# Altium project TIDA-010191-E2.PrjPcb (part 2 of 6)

## Sheet TIDA-010191-E2_LMK04832.SchDoc: LMK0482x
size 558 x 431 mm; Date: Not shown in title block; ApprovedBy: Not shown in title block; CheckedBy: Not shown in title block; Author: Not shown in title block; CompanyName: Not shown in title block; DrawnBy: Avinash N; Engineer: Not shown in title block; Organization: Not shown in title block; Address1: Not shown in title block; Address2: Not shown in title block; Address3: Not shown in title block; Address4: Not shown in title block; DocumentNumber: 2; Revision: Use project parameter SCH_Rev; SheetNumber: 2; SheetTotal: 9; PageSetup: Record=PageOptions¦CenterHorizontal=True¦CenterVertical=True¦PrintScale=1.00¦XCorrection=1.00¦YCorrection=1.00¦PrintKind=0¦BorderSize=5000000¦LeftOffset=0¦BottomOffset=0¦Orientation=2¦PaperLength=1000¦PaperWidth=1000¦Scale=100¦PaperSource=15¦PrintQuality=600¦MediaType=1¦DitherType=10¦PaperKind=Letter¦PrintScaleMode=1
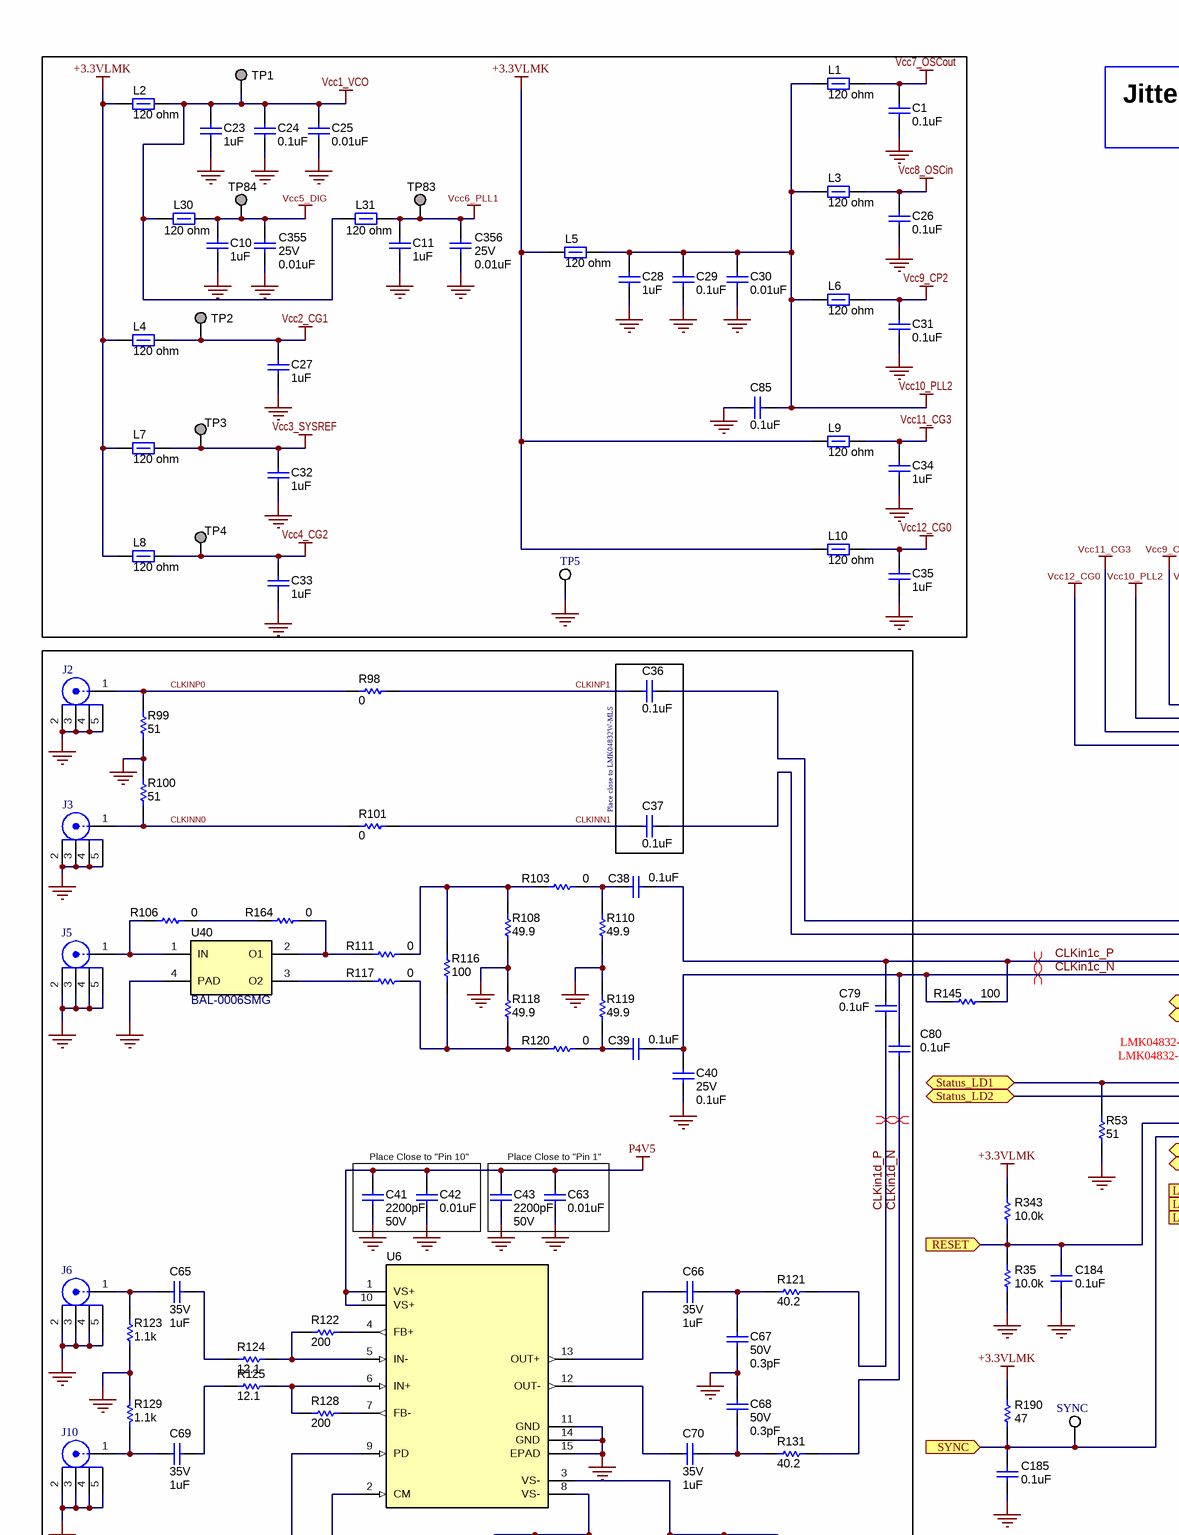
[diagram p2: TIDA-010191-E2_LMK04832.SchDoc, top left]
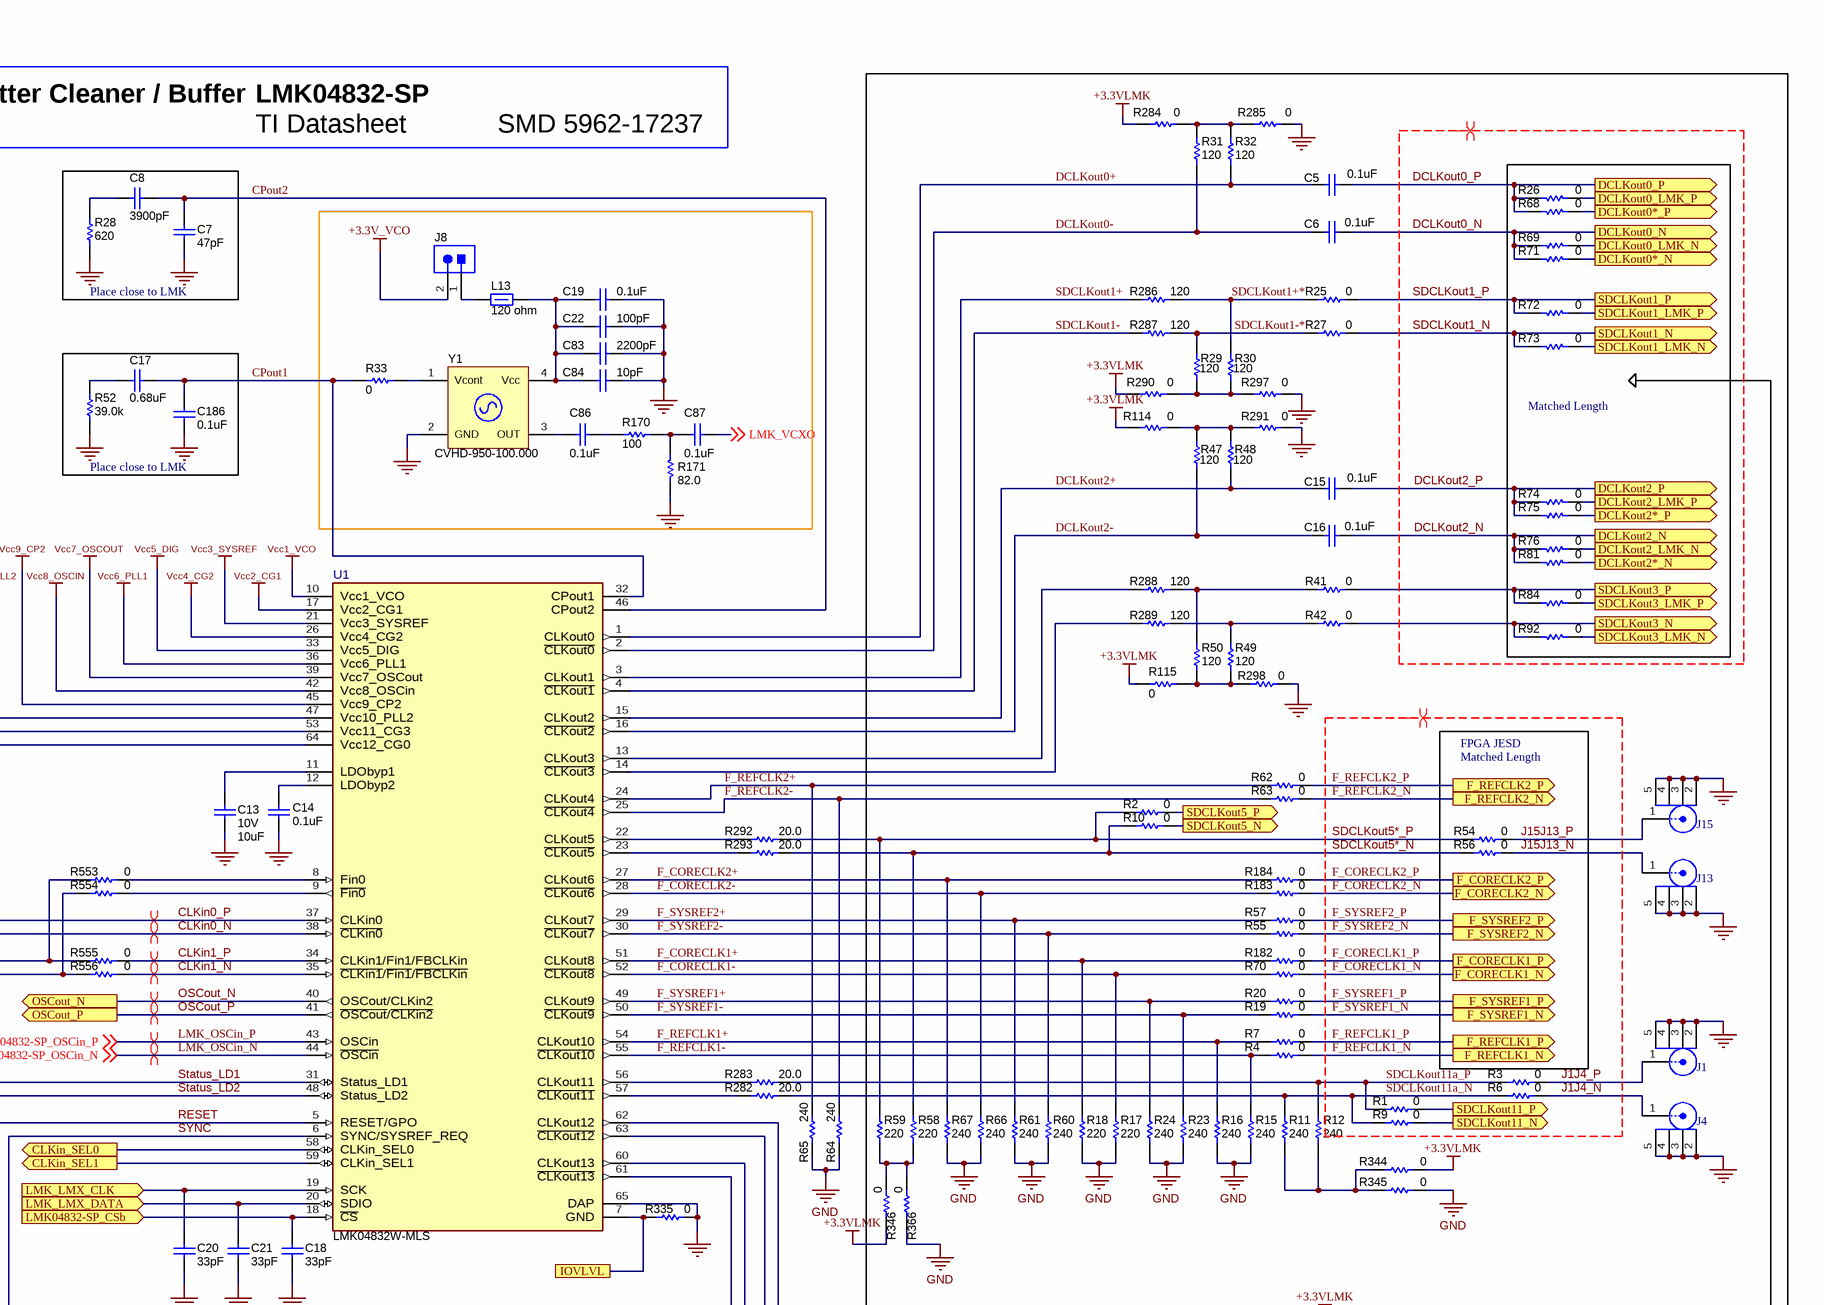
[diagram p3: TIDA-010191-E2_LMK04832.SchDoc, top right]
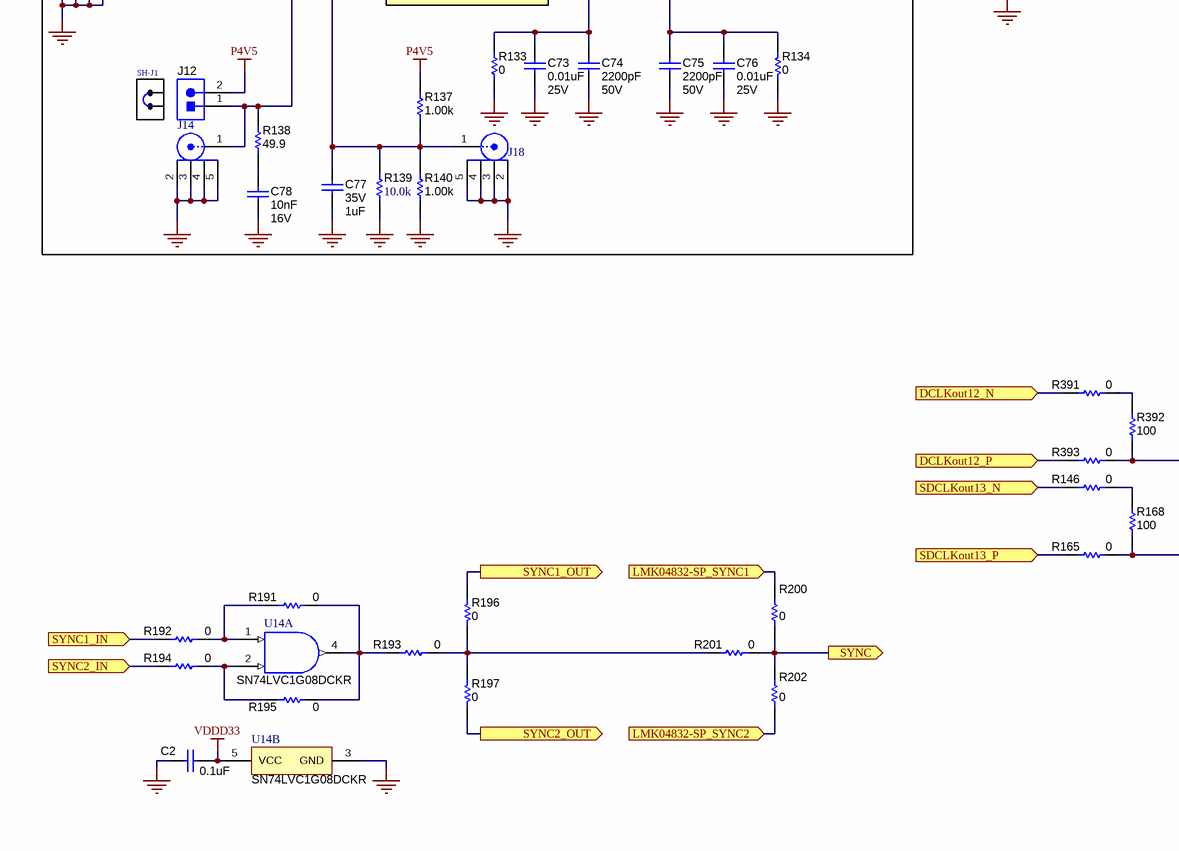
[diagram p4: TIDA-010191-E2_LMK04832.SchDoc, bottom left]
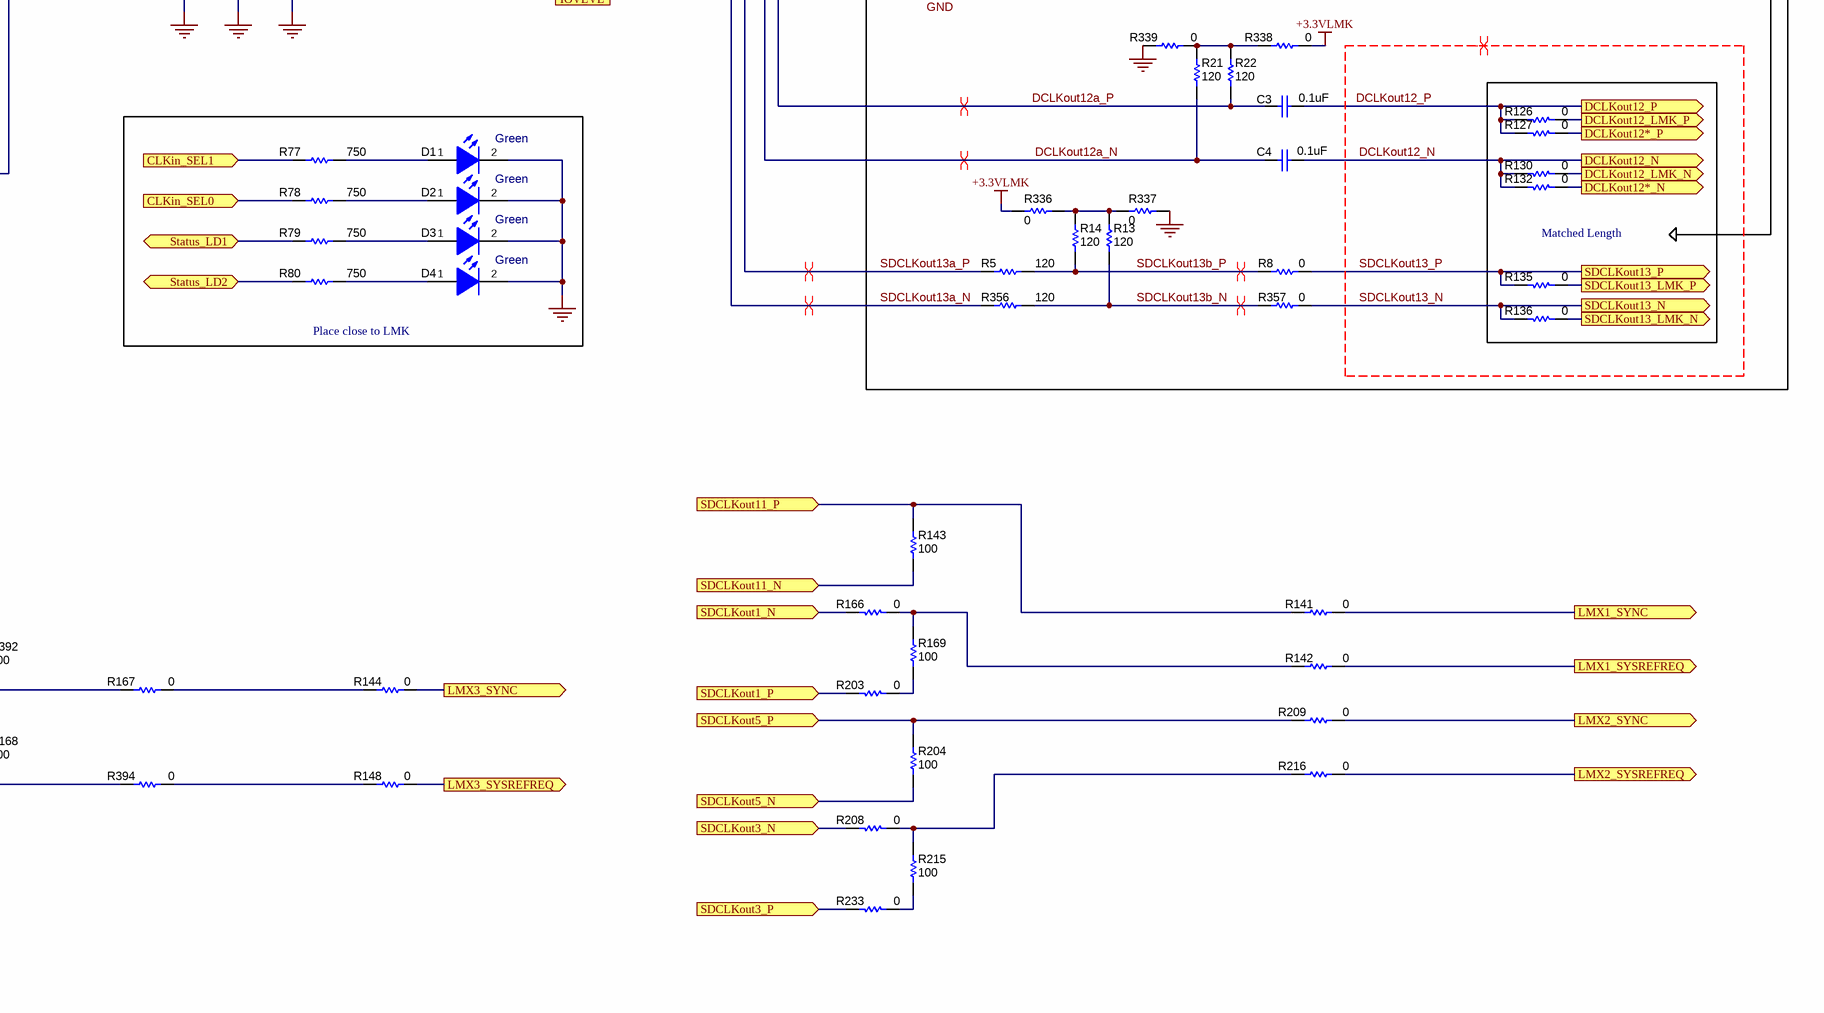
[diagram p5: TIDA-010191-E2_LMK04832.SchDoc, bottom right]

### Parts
C1  ValueDisplayed: 0.1uF  [0402]  (hidden comment: Capacitor)
C2  ValueDisplayed: 0.1uF  [0402]  (hidden comment: Capacitor)
C3  ValueDisplayed: 0.1uF  [0402]  (hidden comment: Capacitor)
C4  ValueDisplayed: 0.1uF  [0402]  (hidden comment: Capacitor)
C5  ValueDisplayed: 0.1uF  [0402]  (hidden comment: Capacitor)
C6  ValueDisplayed: 0.1uF  [0402]  (hidden comment: Capacitor)
C7  ValueDisplayed: 47pF  [0201_033]  (hidden comment: Capacitor)
C8  ValueDisplayed: 3900pF  [0201]  (hidden comment: Capacitor)
C10  ValueDisplayed: 1uF  [0402]  (hidden comment: Capacitor)
C11  ValueDisplayed: 1uF  [0402]  (hidden comment: Capacitor)
C13  VDC_V: 10V  ValueDisplayed: 10uF  [0805_HV]  (hidden comment: CMP-0007732-2)
C14  ValueDisplayed: 0.1uF  [0603]  (hidden comment: Capacitor)
C15  ValueDisplayed: 0.1uF  [0402]  (hidden comment: Capacitor)
C16  ValueDisplayed: 0.1uF  [0402]  (hidden comment: Capacitor)
C17  ValueDisplayed: 0.68uF  [0402]  (hidden comment: Capacitor)
C18  ValueDisplayed: 33pF  [0603L]  (hidden comment: Capacitor)
C19  ValueDisplayed: 0.1uF  [0402]  (hidden comment: Capacitor)
C20  ValueDisplayed: 33pF  [0603L]  (hidden comment: Capacitor)
C21  ValueDisplayed: 33pF  [0603L]  (hidden comment: Capacitor)
C22  ValueDisplayed: 100pF  [0402]  (hidden comment: CMP-0006196-2)
C23  ValueDisplayed: 1uF  [0402]  (hidden comment: Capacitor)
C24  ValueDisplayed: 0.1uF  [0402]  (hidden comment: Capacitor)
C25  ValueDisplayed: 0.01uF  [0402]  (hidden comment: Capacitor)
C26  ValueDisplayed: 0.1uF  [0402]  (hidden comment: Capacitor)
C27  ValueDisplayed: 1uF  [0402]  (hidden comment: Capacitor)
C28  ValueDisplayed: 1uF  [0402]  (hidden comment: Capacitor)
C29  ValueDisplayed: 0.1uF  [0402]  (hidden comment: Capacitor)
C30  ValueDisplayed: 0.01uF  [0402]  (hidden comment: Capacitor)
C31  ValueDisplayed: 0.1uF  [0402]  (hidden comment: Capacitor)
C32  ValueDisplayed: 1uF  [0402]  (hidden comment: Capacitor)
C33  ValueDisplayed: 1uF  [0402]  (hidden comment: Capacitor)
C34  ValueDisplayed: 1uF  [0402]  (hidden comment: Capacitor)
C35  ValueDisplayed: 1uF  [0402]  (hidden comment: Capacitor)
C36  ValueDisplayed: 0.1uF  [0201_033]  (hidden comment: Capacitor)
C37  ValueDisplayed: 0.1uF  [0201_033]  (hidden comment: Capacitor)
C38  ValueDisplayed: 0.1uF  [0402]  (hidden comment: Capacitor)
C39  ValueDisplayed: 0.1uF  [0402]  (hidden comment: Capacitor)
C40  VDC_V: 25V  ValueDisplayed: 0.1uF  [0402]  (hidden comment: CMP-0006295-2)
C41  ValueDisplayed: 2200pF  VDC_V: 50V  [0306]  (hidden comment: CMP-0009493-2)
C42  ValueDisplayed: 0.01uF  [0306]  (hidden comment: Capacitor)
C43  ValueDisplayed: 2200pF  VDC_V: 50V  [0306]  (hidden comment: CMP-0009493-2)
C63  ValueDisplayed: 0.01uF  [0306]  (hidden comment: Capacitor)
C65  VDC_V: 35V  ValueDisplayed: 1uF  [0402]  (hidden comment: GRM155R6YA105KE11D)
C66  VDC_V: 35V  ValueDisplayed: 1uF  [0402]  (hidden comment: GRM155R6YA105KE11D)
C67  VDC_V: 50V  ValueDisplayed: 0.3pF  [0402]  (hidden comment: 500R07S0R3BV4T)
C68  VDC_V: 50V  ValueDisplayed: 0.3pF  [0402]  (hidden comment: 500R07S0R3BV4T)
C69  VDC_V: 35V  ValueDisplayed: 1uF  [0402]  (hidden comment: GRM155R6YA105KE11D)
C70  VDC_V: 35V  ValueDisplayed: 1uF  [0402]  (hidden comment: GRM155R6YA105KE11D)
C73  ValueDisplayed: 0.01uF  VDC_V: 25V  [0306]  (hidden comment: CMP-0009490-2)
C74  ValueDisplayed: 2200pF  VDC_V: 50V  [0306]  (hidden comment: CMP-0009493-2)
C75  ValueDisplayed: 2200pF  VDC_V: 50V  [0306]  (hidden comment: CMP-0009493-2)
C76  ValueDisplayed: 0.01uF  VDC_V: 25V  [0306]  (hidden comment: CMP-0009490-2)
C77  VDC_V: 35V  ValueDisplayed: 1uF  [0402]  (hidden comment: GRM155R6YA105KE11D)
C78  Cap_F: 10nF  VDC_V: 16V  [0603]  (hidden comment: GRM188R71C103KA01D)
C79  ValueDisplayed: 0.1uF  [0402]  (hidden comment: Capacitor)
C80  ValueDisplayed: 0.1uF  [0402]  (hidden comment: Capacitor)
C83  ValueDisplayed: 2200pF  [0402]  (hidden comment: Capacitor)
C84  ValueDisplayed: 10pF  [0402]  (hidden comment: Capacitor)
C85  ValueDisplayed: 0.1uF  [0402]  (hidden comment: Capacitor)
C86  ValueDisplayed: 0.1uF  [0402]  (hidden comment: Capacitor)
C87  ValueDisplayed: 0.1uF  [0402]  (hidden comment: Capacitor)
C184  ValueDisplayed: 0.1uF  [0402]  (hidden comment: Capacitor)
C185  ValueDisplayed: 0.1uF  [0402]  (hidden comment: Capacitor)
C186  ValueDisplayed: 0.1uF  [0402]  (hidden comment: Capacitor)
C355  VDC_V: 25V  ValueDisplayed: 0.01uF  [0402]  (hidden comment: GRM155R71E103KA01D)
C356  VDC_V: 25V  ValueDisplayed: 0.01uF  [0402]  (hidden comment: GRM155R71E103KA01D)
D1  value Green  [LTST-C191_Green]  (hidden comment: LED)
D2  value Green  [LTST-C191_Green]  (hidden comment: LED)
D3  value Green  [LTST-C191_Green]  (hidden comment: LED)
D4  value Green  [LTST-C191_Green]  (hidden comment: LED)
J1  SMA_Contact1_GND2345  [Johnson_142-0701-20x]  (value not drawn)
J2  SMA_Contact1_GND2345  [Johnson_142-0701-20x]  (value not drawn)
J3  SMA_Contact1_GND2345  [Johnson_142-0701-20x]  (value not drawn)
J4  SMA_Contact1_GND2345  [Johnson_142-0701-20x]  (value not drawn)
J5  SMA_Contact1_GND2345  [Johnson_142-0701-20x]  (value not drawn)
J6  SMA_Contact1_GND2345  [Johnson_142-0701-20x]  (value not drawn)
J8  HTSW-102-07-G-S  [Samtec_HTSW-102-07-G-S]  (value not drawn)
J10  SMA_Contact1_GND2345  [Johnson_142-0701-20x]  (value not drawn)
J12  HTSW-102-07-G-S  [Samtec_HTSW-102-07-G-S]  (value not drawn)
J13  SMA_Contact1_GND2345  [Johnson_142-0701-20x]  (value not drawn)
J14  SMA_Contact1_GND2345  [Johnson_142-0701-20x]  (value not drawn)
J15  SMA_Contact1_GND2345  [Johnson_142-0701-20x]  (value not drawn)
J18  SMA_Contact1_GND2345  [Johnson_142-0701-20x]  (value not drawn)
L1  ValueDisplayed: 120 ohm  [0603]  (hidden comment: Ferrite_Bead)
L2  ValueDisplayed: 120 ohm  [0603]  (hidden comment: Ferrite_Bead)
L3  ValueDisplayed: 120 ohm  [0603]  (hidden comment: Ferrite_Bead)
L4  ValueDisplayed: 120 ohm  [0603]  (hidden comment: Ferrite_Bead)
L5  ValueDisplayed: 120 ohm  [0603]  (hidden comment: Ferrite_Bead)
L6  ValueDisplayed: 120 ohm  [0603]  (hidden comment: Ferrite_Bead)
L7  ValueDisplayed: 120 ohm  [0603]  (hidden comment: Ferrite_Bead)
L8  ValueDisplayed: 120 ohm  [0603]  (hidden comment: Ferrite_Bead)
L9  ValueDisplayed: 120 ohm  [0603]  (hidden comment: Ferrite_Bead)
L10  ValueDisplayed: 120 ohm  [0603]  (hidden comment: Ferrite_Bead)
L13  ValueDisplayed: 120 ohm  [0603]  (hidden comment: Ferrite_Bead)
L30  ValueDisplayed: 120 ohm  [0603]  (hidden comment: Ferrite_Bead)
L31  ValueDisplayed: 120 ohm  [0603]  (hidden comment: Ferrite_Bead)
R1  ValueDisplayed: 0  [0402]  (hidden comment: Resistor)
R2  ValueDisplayed: 0  [0402]  (hidden comment: Resistor)
R3  ValueDisplayed: 0  [0402]  (hidden comment: Resistor)
R4  ValueDisplayed: 0  [0402]  (hidden comment: Resistor)
R5  ValueDisplayed: 120  [0402]  (hidden comment: Resistor)
R6  ValueDisplayed: 0  [0402]  (hidden comment: Resistor)
R7  ValueDisplayed: 0  [0402]  (hidden comment: Resistor)
R8  ValueDisplayed: 0  [0402]  (hidden comment: Resistor)
R9  ValueDisplayed: 0  [0402]  (hidden comment: Resistor)
R10  ValueDisplayed: 0  [0402]  (hidden comment: Resistor)
R11  ValueDisplayed: 240  [0402]  (hidden comment: Resistor)
R12  ValueDisplayed: 240  [0402]  (hidden comment: Resistor)
R13  ValueDisplayed: 120  [0402]  (hidden comment: Resistor)
R14  ValueDisplayed: 120  [0402]  (hidden comment: Resistor)
R15  ValueDisplayed: 240  [0402]  (hidden comment: Resistor)
R16  ValueDisplayed: 240  [0402]  (hidden comment: Resistor)
R17  ValueDisplayed: 220  [0402]  (hidden comment: Resistor)
R18  ValueDisplayed: 220  [0402]  (hidden comment: Resistor)
R19  ValueDisplayed: 0  [0402]  (hidden comment: Resistor)
R20  ValueDisplayed: 0  [0402]  (hidden comment: Resistor)
R21  ValueDisplayed: 120  [0402]  (hidden comment: Resistor)
R22  ValueDisplayed: 120  [0402]  (hidden comment: Resistor)
R23  ValueDisplayed: 240  [0402]  (hidden comment: Resistor)
R24  ValueDisplayed: 240  [0402]  (hidden comment: Resistor)
R25  ValueDisplayed: 0  [0402]  (hidden comment: Resistor)
R26  ValueDisplayed: 0  [0402]  (hidden comment: CMP-0026822-3)
R27  ValueDisplayed: 0  [0402]  (hidden comment: Resistor)
R28  ValueDisplayed: 620  [0201]  (hidden comment: Resistor)
R29  ValueDisplayed: 120  [0402]  (hidden comment: Resistor)
R30  ValueDisplayed: 120  [0402]  (hidden comment: Resistor)
R31  ValueDisplayed: 120  [0402]  (hidden comment: Resistor)
R32  ValueDisplayed: 120  [0402]  (hidden comment: Resistor)
R33  ValueDisplayed: 0  [0402]  (hidden comment: Resistor)
R35  ValueDisplayed: 10.0k  [0402]  (hidden comment: Resistor)
R41  ValueDisplayed: 0  [0402]  (hidden comment: Resistor)
R42  ValueDisplayed: 0  [0402]  (hidden comment: Resistor)
R47  ValueDisplayed: 120  [0402]  (hidden comment: Resistor)
R48  ValueDisplayed: 120  [0402]  (hidden comment: Resistor)
R49  ValueDisplayed: 120  [0402]  (hidden comment: Resistor)
R50  ValueDisplayed: 120  [0402]  (hidden comment: Resistor)
R52  ValueDisplayed: 39.0k  [0201]  (hidden comment: Resistor)
R53  value 51  [0603L]  (hidden comment: Resistor)
R54  ValueDisplayed: 0  [0402]  (hidden comment: Resistor)
R55  ValueDisplayed: 0  [0402]  (hidden comment: Resistor)
R56  ValueDisplayed: 0  [0402]  (hidden comment: Resistor)
R57  ValueDisplayed: 0  [0402]  (hidden comment: Resistor)
R58  ValueDisplayed: 220  [0402]  (hidden comment: Resistor)
R59  ValueDisplayed: 220  [0402]  (hidden comment: Resistor)
R60  ValueDisplayed: 240  [0402]  (hidden comment: Resistor)
R61  ValueDisplayed: 240  [0402]  (hidden comment: Resistor)
R62  ValueDisplayed: 0  [0402]  (hidden comment: Resistor)
R63  ValueDisplayed: 0  [0402]  (hidden comment: Resistor)
R64  ValueDisplayed: 240  [0402]  (hidden comment: Resistor)
R65  ValueDisplayed: 240  [0402]  (hidden comment: Resistor)
R66  ValueDisplayed: 240  [0402]  (hidden comment: Resistor)
R67  ValueDisplayed: 240  [0402]  (hidden comment: Resistor)
R68  ValueDisplayed: 0  [0402]  (hidden comment: CMP-0026822-3)
R69  ValueDisplayed: 0  [0402]  (hidden comment: CMP-0026822-3)
R70  ValueDisplayed: 0  [0402]  (hidden comment: Resistor)
R71  ValueDisplayed: 0  [0402]  (hidden comment: CMP-0026822-3)
R72  ValueDisplayed: 0  [0402]  (hidden comment: CMP-0026822-3)
R73  ValueDisplayed: 0  [0402]  (hidden comment: CMP-0026822-3)
R74  ValueDisplayed: 0  [0402]  (hidden comment: CMP-0026822-3)
R75  ValueDisplayed: 0  [0402]  (hidden comment: CMP-0026822-3)
R76  ValueDisplayed: 0  [0402]  (hidden comment: CMP-0026822-3)
R77  ValueDisplayed: 750  [0603]  (hidden comment: Resistor)
R78  ValueDisplayed: 750  [0603]  (hidden comment: Resistor)
R79  ValueDisplayed: 750  [0603]  (hidden comment: Resistor)
R80  ValueDisplayed: 750  [0603]  (hidden comment: Resistor)
R81  ValueDisplayed: 0  [0402]  (hidden comment: CMP-0026822-3)
R84  ValueDisplayed: 0  [0402]  (hidden comment: CMP-0026822-3)
R92  ValueDisplayed: 0  [0402]  (hidden comment: CMP-0026822-3)
R98  ValueDisplayed: 0  [0201]  (hidden comment: CMP-0065361-1)
R99  ValueDisplayed: 51  [0201]  (hidden comment: RC0201JR-0751RL)
R100  ValueDisplayed: 51  [0201]  (hidden comment: RC0201JR-0751RL)
R101  ValueDisplayed: 0  [0201]  (hidden comment: CMP-0065361-1)
R103  ValueDisplayed: 0  [0201]  (hidden comment: ERJ-1GN0R00C)
R106  ValueDisplayed: 0  [0201]  (hidden comment: ERJ-1GN0R00C)
R108  ValueDisplayed: 49.9  [0603]  (hidden comment: CRCW060349R9FKEA)
R110  ValueDisplayed: 49.9  [0603]  (hidden comment: CRCW060349R9FKEA)
R111  ValueDisplayed: 0  [0201]  (hidden comment: ERJ-1GN0R00C)
R114  ValueDisplayed: 0  [0402]  (hidden comment: Resistor)
R115  ValueDisplayed: 0  [0402]  (hidden comment: Resistor)
R116  ValueDisplayed: 100  [0402]  (hidden comment: CRCW0402100RFKED)
R117  ValueDisplayed: 0  [0201]  (hidden comment: ERJ-1GN0R00C)
R118  ValueDisplayed: 49.9  [0603]  (hidden comment: CRCW060349R9FKEA)
R119  ValueDisplayed: 49.9  [0603]  (hidden comment: CRCW060349R9FKEA)
R120  ValueDisplayed: 0  [0201]  (hidden comment: ERJ-1GN0R00C)
R121  ValueDisplayed: 40.2  [0402]  (hidden comment: CRCW040240R2FKED)
R122  ValueDisplayed: 200  [0402]  (hidden comment: CRCW0402200RFKED)
R123  ValueDisplayed: 1.1k  [0402]  (hidden comment: CRCW04021K10JNED)
R124  ValueDisplayed: 12.1  [0402]  (hidden comment: CRCW040212R1FKED)
R125  ValueDisplayed: 12.1  [0402]  (hidden comment: CRCW040212R1FKED)
R126  ValueDisplayed: 0  [0402]  (hidden comment: CMP-0026822-3)
R127  ValueDisplayed: 0  [0402]  (hidden comment: CMP-0026822-3)
R128  ValueDisplayed: 200  [0402]  (hidden comment: CRCW0402200RFKED)
R129  ValueDisplayed: 1.1k  [0402]  (hidden comment: CRCW04021K10JNED)
R130  ValueDisplayed: 0  [0402]  (hidden comment: CMP-0026822-3)
R131  ValueDisplayed: 40.2  [0402]  (hidden comment: CRCW040240R2FKED)
R132  ValueDisplayed: 0  [0402]  (hidden comment: CMP-0026822-3)
R133  ValueDisplayed: 0  [0402]  (hidden comment: CRCW04020000Z0ED)
R134  ValueDisplayed: 0  [0402]  (hidden comment: CRCW04020000Z0ED)
R135  ValueDisplayed: 0  [0402]  (hidden comment: CMP-0026822-3)
R136  ValueDisplayed: 0  [0402]  (hidden comment: CMP-0026822-3)
R137  ValueDisplayed: 1.00k  [0603]  (hidden comment: CRCW06031K00FKEA)
R138  ValueDisplayed: 49.9  [0603]  (hidden comment: CRCW060349R9FKEA)
R139  ValueDisplayed: 10.0k  [0402]  (hidden comment: ERJ-2RKF1002X)
R140  ValueDisplayed: 1.00k  [0603]  (hidden comment: CRCW06031K00FKEA)
R141  ValueDisplayed: 0  [0402]  (hidden comment: Resistor)
R142  ValueDisplayed: 0  [0402]  (hidden comment: Resistor)
R143  ValueDisplayed: 100  [0402]  (hidden comment: CRCW0402100RFKED)
R144  ValueDisplayed: 0  [0402]  (hidden comment: Resistor)
R145  ValueDisplayed: 100  [0402]  (hidden comment: CRCW0402100RFKED)
R146  ValueDisplayed: 0  [0402]  (hidden comment: Resistor)
R148  ValueDisplayed: 0  [0402]  (hidden comment: Resistor)
R164  ValueDisplayed: 0  [0201]  (hidden comment: ERJ-1GN0R00C)
R165  ValueDisplayed: 0  [0402]  (hidden comment: Resistor)
R166  ValueDisplayed: 0  [0402]  (hidden comment: CMP-0026822-3)
R167  ValueDisplayed: 0  [0402]  (hidden comment: Resistor)
R168  ValueDisplayed: 100  [0402]  (hidden comment: CRCW0402100RFKED)
R169  ValueDisplayed: 100  [0402]  (hidden comment: CRCW0402100RFKED)
R170  ValueDisplayed: 100  [0402]  (hidden comment: CRCW0402100RFKED)
R171  ValueDisplayed: 82.0  [0603]  (hidden comment: Resistor)
R182  ValueDisplayed: 0  [0402]  (hidden comment: Resistor)
R183  ValueDisplayed: 0  [0402]  (hidden comment: Resistor)
R184  ValueDisplayed: 0  [0402]  (hidden comment: Resistor)
R190  ValueDisplayed: 47  [0402]  (hidden comment: Resistor)
R191  ValueDisplayed: 0  [0402]  (hidden comment: Resistor)
R192  ValueDisplayed: 0  [0402]  (hidden comment: Resistor)
R193  ValueDisplayed: 0  [0402]  (hidden comment: Resistor)
R194  ValueDisplayed: 0  [0402]  (hidden comment: Resistor)
R195  ValueDisplayed: 0  [0402]  (hidden comment: Resistor)
R196  ValueDisplayed: 0  [0402]  (hidden comment: Resistor)
R197  ValueDisplayed: 0  [0402]  (hidden comment: Resistor)
R200  ValueDisplayed: 0  [0402]  (hidden comment: Resistor)
R201  ValueDisplayed: 0  [0402]  (hidden comment: Resistor)
R202  ValueDisplayed: 0  [0402]  (hidden comment: Resistor)
R203  ValueDisplayed: 0  [0402]  (hidden comment: CMP-0026822-3)
R204  ValueDisplayed: 100  [0402]  (hidden comment: CRCW0402100RFKED)
R208  ValueDisplayed: 0  [0402]  (hidden comment: CMP-0026822-3)
R209  ValueDisplayed: 0  [0402]  (hidden comment: CMP-0026822-3)
R215  ValueDisplayed: 100  [0402]  (hidden comment: CRCW0402100RFKED)
R216  ValueDisplayed: 0  [0402]  (hidden comment: CMP-0026822-3)
R233  ValueDisplayed: 0  [0402]  (hidden comment: CMP-0026822-3)
R282  ValueDisplayed: 20.0  [0402]  (hidden comment: Resistor)
R283  ValueDisplayed: 20.0  [0402]  (hidden comment: Resistor)
R284  ValueDisplayed: 0  [0402]  (hidden comment: Resistor)
R285  ValueDisplayed: 0  [0402]  (hidden comment: Resistor)
R286  ValueDisplayed: 120  [0402]  (hidden comment: Resistor)
R287  ValueDisplayed: 120  [0402]  (hidden comment: Resistor)
R288  ValueDisplayed: 120  [0402]  (hidden comment: Resistor)
R289  ValueDisplayed: 120  [0402]  (hidden comment: Resistor)
R290  ValueDisplayed: 0  [0402]  (hidden comment: Resistor)
R291  ValueDisplayed: 0  [0402]  (hidden comment: Resistor)
R292  ValueDisplayed: 20.0  [0402]  (hidden comment: Resistor)
R293  ValueDisplayed: 20.0  [0402]  (hidden comment: Resistor)
R297  ValueDisplayed: 0  [0402]  (hidden comment: Resistor)
R298  ValueDisplayed: 0  [0402]  (hidden comment: Resistor)
R335  ValueDisplayed: 0  [0402]  (hidden comment: Resistor)
R336  ValueDisplayed: 0  [0402]  (hidden comment: Resistor)
R337  ValueDisplayed: 0  [0402]  (hidden comment: Resistor)
R338  ValueDisplayed: 0  [0402]  (hidden comment: Resistor)
R339  ValueDisplayed: 0  [0402]  (hidden comment: Resistor)
R343  ValueDisplayed: 10.0k  [0402]  (hidden comment: Resistor)
R344  ValueDisplayed: 0  [0402]  (hidden comment: Resistor)
R345  ValueDisplayed: 0  [0402]  (hidden comment: Resistor)
R346  ValueDisplayed: 0  [0402]  (hidden comment: Resistor)
R356  ValueDisplayed: 120  [0402]  (hidden comment: Resistor)
R357  ValueDisplayed: 0  [0402]  (hidden comment: Resistor)
R366  ValueDisplayed: 0  [0402]  (hidden comment: Resistor)
R391  ValueDisplayed: 0  [0402]  (hidden comment: Resistor)
R392  ValueDisplayed: 100  [0402]  (hidden comment: CRCW0402100RFKED)
R393  ValueDisplayed: 0  [0402]  (hidden comment: Resistor)
R394  ValueDisplayed: 0  [0402]  (hidden comment: Resistor)
R553  ValueDisplayed: 0  [0201]  (hidden comment: ERJ-1GN0R00C)
R554  ValueDisplayed: 0  [0201]  (hidden comment: ERJ-1GN0R00C)
R555  ValueDisplayed: 0  [0201]  (hidden comment: ERJ-1GN0R00C)
R556  ValueDisplayed: 0  [0201]  (hidden comment: ERJ-1GN0R00C)
SH-J1  SPC02SYAN  [SPC02SYAN]  (value not drawn)
SYNC  5007  [Keystone5007]  (value not drawn)
TP1  1573-2  [Keystone1573-2]  (value not drawn)
TP2  1573-2  [Keystone1573-2]  (value not drawn)
TP3  1573-2  [Keystone1573-2]  (value not drawn)
TP4  1573-2  [Keystone1573-2]  (value not drawn)
TP5  5015  [Testpoint_Keystone_Miniature]  (value not drawn)
TP83  1573-2  [Keystone1573-2]  (value not drawn)
TP84  1573-2  [Keystone1573-2]  (value not drawn)
U1  LMK04832W-MLS  [HBE0064A-MFG]
U6  LMH5401FFK/EM  [FFK0014A]  (value not drawn)
U14  SN74LVC1G08DCKR  [DCK0005A_N]  (parts A,B of 2)
U40  BAL-0006SMG  [Marki_BAL-0006SMG]
Y1  PartNumber: CVHD-950-100.000  [OSC_CVHD-950-4]  (hidden comment: CMP-0006073-3)

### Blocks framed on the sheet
Place close to LMK: C7 C8 R28
Matched Length: R26 R68 R69 R71-R76 R81 R84 R92
Place close to LMK: C17 C186 R52
Place close to LMK04832W-MLS: C36 C37
Place Close to "Pin 10": C41 C42
Place Close to "Pin 1": C43 C63
Matched Length: R126 R127 R130 R132 R135 R136
Place close to LMK: D1-D4 R77-R80

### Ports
CLKin_SEL0 (in), CLKin_SEL0 (out), CLKin_SEL1 (in), CLKin_SEL1 (out), DCLKout0*_N (out), DCLKout0*_P (out), DCLKout0_LMK_N (out), DCLKout0_LMK_P (out), DCLKout0_N (out), DCLKout0_P (out), DCLKout2*_N (out), DCLKout2*_P (out), DCLKout2_LMK_N (out), DCLKout2_LMK_P (out), DCLKout2_N (out), DCLKout2_P (out), DCLKout12*_N (out), DCLKout12*_P (out), DCLKout12_LMK_N (out), DCLKout12_LMK_P (out), DCLKout12_N (in), DCLKout12_N (out), DCLKout12_P (in), DCLKout12_P (out), F_CORECLK1_N (out), F_CORECLK1_P (out), F_CORECLK2_N (out), F_CORECLK2_P (out), F_REFCLK1_N (out), F_REFCLK1_P (out), F_REFCLK2_N (out), F_REFCLK2_P (out), F_SYSREF1_N (out), F_SYSREF1_P (out), F_SYSREF2_N (out), F_SYSREF2_P (out), IOVLVL, LMK04832-SP_CSb (in), LMK04832-SP_SYNC1 (in), LMK04832-SP_SYNC2 (in), LMK_LMX_CLK (in), LMK_LMX_DATA (in), LMX1_SYNC (out), LMX1_SYSREFREQ (out), LMX2_SYNC (out), LMX2_SYSREFREQ (out), LMX3_SYNC (out), LMX3_SYSREFREQ (out), OSCout_N (out), OSCout_P (out), RESET (in), SDCLKout1_LMK_N (out), SDCLKout1_LMK_P (out), SDCLKout1_N (in), SDCLKout1_N (out), SDCLKout1_P (in), SDCLKout1_P (out), SDCLKout3_LMK_N (out), SDCLKout3_LMK_P (out), SDCLKout3_N (in), SDCLKout3_N (out), SDCLKout3_P (in), SDCLKout3_P (out), SDCLKout5_N (in), SDCLKout5_N (out), SDCLKout5_P (in), SDCLKout5_P (out), SDCLKout11_N (in), SDCLKout11_N (out), SDCLKout11_P (in), SDCLKout11_P (out), SDCLKout13_LMK_N (out), SDCLKout13_LMK_P (out), SDCLKout13_N (in), SDCLKout13_N (out), SDCLKout13_P (in), SDCLKout13_P (out), Status_LD1 (bidir), Status_LD2 (bidir), SYNC1_IN (in), SYNC1_OUT (out), SYNC2_IN (in), SYNC2_OUT (out), SYNC (in), SYNC (out)

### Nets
+3.3V_VCO: J8.2
+3.3VLMK: L2.2 L4.2 L5.2 L7.2 L8.2 L9.2 L10.2 R114.2 R115.2 R190.2 R284.2 R290.2 R336.1 R338.2 R343.2 R344.2 R346.1
GND: C1.2 C2.2 C7.2 C10.2 C11.2 C13.1 C14.2 C18.1 C19.1 C20.1 C21.1 C22.1 C23.2 C24.2 C25.2 C26.1 C27.2 C28.2 C29.2 C30.2 C31.1 C32.2 C33.2 C34.2 C35.2 C40.1 C41.2 C42.1 C43.2 C63.2 C67.2 C68.2 C73.1 C74.2 C75.2 C76.1 C77.2 C78.2 C83.1 C84.1 C85.1 C184.2 C185.2 C186.1 C355.2 C356.2 D1.2(K) D2.2(K) D3.2(K) D4.2(K) J1.2 J1.3 J1.4 J1.5 J2.2 J2.3 J2.4 J2.5 J3.2 J3.3 J3.4 J3.5 J4.2 J4.3 J4.4 J4.5 J5.2 J5.3 J5.4 J5.5 J6.2 J6.3 J6.4 J6.5 J10.2 J10.3 J10.4 J10.5 J13.2 J13.3 J13.4 J13.5 J14.2 J14.3 J14.4 J14.5 J15.2 J15.3 J15.4 J15.5 J18.2 J18.3 J18.4 J18.5 R15.1 R16.1 R17.1 R18.1 R23.1 R24.1 R28.1 R35.1 R52.1 R53.2 R60.2 R61.2 R64.2 R65.2 R66.1 R67.1 R99.1 R100.2 R108.1 R110.1 R118.2 R119.2 R123.1 R129.1 R133.1 R134.1 R139.1 R140.1 R171.1 R285.1 R291.1 R297.1 R298.1 R335.2 R337.1 R339.2 R345.1 R366.2 TP5.1 U1.65(DAP) U6.11(GND) U6.14(GND) U6.15(EPAD) U14.3(GND) U40.4(PAD) Y1.2(GND)
P4V5: C41.1 C42.2 C43.1 C63.1 J12.2 R137.1 U6.1(VS+) U6.10(VS+)
Vcc1_VCO: C23.1 C24.1 C25.1 L2.1 L30.2 L31.2 TP1.1 U1.10(Vcc1_VCO)
Vcc2_CG1: C27.1 L4.1 TP2.1 U1.17(Vcc2_CG1)
Vcc3_SYSREF: C32.1 L7.1 TP3.1 U1.21(Vcc3_SYSREF)
Vcc4_CG2: C33.1 L8.1 TP4.1 U1.26(Vcc4_CG2)
Vcc5_DIG: C10.1 C355.1 L30.1 TP84.1 U1.33(Vcc5_DIG)
Vcc6_PLL1: C11.1 C356.1 L31.1 TP83.1 U1.36(Vcc6_PLL1)
Vcc7_OSCOUT: C1.1 L1.1 U1.39(Vcc7_OSCout)
Vcc8_OSCIN: C26.2 L3.1 U1.42(Vcc8_OSCin)
Vcc9_CP2: C31.2 L6.1 U1.45(Vcc9_CP2)
Vcc10_PLL2: C28.1 C29.1 C30.1 C85.2 L1.2 L3.2 L5.1 L6.2 U1.47(Vcc10_PLL2)
Vcc11_CG3: C34.1 L9.1 U1.53(Vcc11_CG3)
Vcc12_CG0: C35.1 L10.1 U1.64(Vcc12_CG0)
VDDD33: C2.1 U14.5(VCC)
CLKin0_N: C37.2 U1.38(~{CLKin0})
CLKin0_P: C36.2 U1.37(CLKin0)
CLKin1_N: R556.2 U1.35(~{CLKin1}/~{Fin1}/~{FBCLKin})
CLKin1_P: R555.2 U1.34(CLKin1/Fin1/FBCLKin)
CLKin1c_N: C39.2 C40.2 C80.2 R145.2 R554.1 R556.1
CLKin1c_P: C38.2 C79.2 R145.1 R553.1 R555.1
CLKin1d_N: C80.1 R131.2
CLKin1d_P: C79.1 R121.2
CLKin_SEL0: R78.1 U1.58(CLKin_SEL0) ; port CLKin_SEL0
CLKin_SEL1: R77.1 U1.59(CLKin_SEL1) ; port CLKin_SEL1
CLKINN0: J3.1 R100.1 R101.1
CLKINN1: C37.1 R101.2
CLKINP0: J2.1 R98.1 R99.2
CLKINP1: C36.1 R98.2
CPout1: C17.1 C186.2 R33.2 U1.32(CPout1)
CPout2: C7.1 C8.2 U1.46(CPout2)
DCLKout0*_N: R71.1 ; port DCLKout0*_N
DCLKout0*_P: R68.1 ; port DCLKout0*_P
DCLKout0+: C5.1 R32.2 U1.1(CLKout0)
DCLKout0-: C6.1 R31.2 U1.2(~{CLKout0})
DCLKout0_LMK_N: R69.1 ; port DCLKout0_LMK_N
DCLKout0_LMK_P: R26.1 ; port DCLKout0_LMK_P
DCLKout0_N: C6.2 R69.2 R71.2 ; port DCLKout0_N
DCLKout0_P: C5.2 R26.2 R68.2 ; port DCLKout0_P
DCLKout2*_N: R81.1 ; port DCLKout2*_N
DCLKout2*_P: R75.1 ; port DCLKout2*_P
DCLKout2+: C15.1 R48.2 U1.15(CLKout2)
DCLKout2-: C16.1 R47.2 U1.16(~{CLKout2})
DCLKout2_LMK_N: R76.1 ; port DCLKout2_LMK_N
DCLKout2_LMK_P: R74.1 ; port DCLKout2_LMK_P
DCLKout2_N: C16.2 R76.2 R81.2 ; port DCLKout2_N
DCLKout2_P: C15.2 R74.2 R75.2 ; port DCLKout2_P
DCLKout12*_N: R132.1 ; port DCLKout12*_N
DCLKout12*_P: R127.1 ; port DCLKout12*_P
DCLKout12_LMK_N: R130.1 ; port DCLKout12_LMK_N
DCLKout12_LMK_P: R126.1 ; port DCLKout12_LMK_P
DCLKout12_N: C4.2 R130.2 R132.2 R391.1 ; port DCLKout12_N
DCLKout12_P: C3.2 R126.2 R127.2 R393.1 ; port DCLKout12_P
DCLKout12a_N: C4.1 R21.2 U1.63(~{CLKout12})
DCLKout12a_P: C3.1 R22.2 U1.62(CLKout12)
F_CORECLK1+: R18.2 R182.1 U1.51(CLKout8)
F_CORECLK1-: R17.2 R70.1 U1.52(~{CLKout8})
F_CORECLK1_N: R70.2 ; port F_CORECLK1_N
F_CORECLK1_P: R182.2 ; port F_CORECLK1_P
F_CORECLK2+: R67.2 R184.1 U1.27(CLKout6)
F_CORECLK2-: R66.2 R183.1 U1.28(~{CLKout6})
F_CORECLK2_N: R183.2 ; port F_CORECLK2_N
F_CORECLK2_P: R184.2 ; port F_CORECLK2_P
F_REFCLK1+: R7.1 R16.2 U1.54(CLKout10)
F_REFCLK1-: R4.1 R15.2 U1.55(~{CLKout10})
F_REFCLK1_N: R4.2 ; port F_REFCLK1_N
F_REFCLK1_P: R7.2 ; port F_REFCLK1_P
F_REFCLK2+: R62.2 R65.1 U1.24(CLKout4)
F_REFCLK2-: R63.2 R64.1 U1.25(~{CLKout4})
F_REFCLK2_N: R63.1 ; port F_REFCLK2_N
F_REFCLK2_P: R62.1 ; port F_REFCLK2_P
F_SYSREF1+: R20.1 R24.2 U1.49(CLKout9)
F_SYSREF1-: R19.1 R23.2 U1.50(~{CLKout9})
F_SYSREF1_N: R19.2 ; port F_SYSREF1_N
F_SYSREF1_P: R20.2 ; port F_SYSREF1_P
F_SYSREF2+: R57.1 R61.1 U1.29(CLKout7)
F_SYSREF2-: R55.1 R60.1 U1.30(~{CLKout7})
F_SYSREF2_N: R55.2 ; port F_SYSREF2_N
F_SYSREF2_P: R57.2 ; port F_SYSREF2_P
IOVLVL: R335.1 U1.7(GND) ; port IOVLVL
J1J4_N: J4.1 R6.1
J1J4_P: J1.1 R3.1
J15J13_N: J13.1 R56.1
J15J13_P: J15.1 R54.1
LMK04832-SP_CSb: C18.2 U1.18(~{CS}) ; port LMK04832-SP_CSb
LMK04832-SP_SYNC1: R200.1 ; port LMK04832-SP_SYNC1
LMK04832-SP_SYNC2: R202.1 ; port LMK04832-SP_SYNC2
LMK_LMX_CLK: C20.2 U1.19(SCK) ; port LMK_LMX_CLK
LMK_LMX_DATA: C21.2 U1.20(SDIO) ; port LMK_LMX_DATA
LMK_OSCin_N: U1.44(~{OSCin}) ; off-sheet LMK04832-SP_OSCin_N  [also labelled LMK04832-SP_OSCin_N]
LMK_OSCin_P: U1.43(OSCin) ; off-sheet LMK04832-SP_OSCin_P  [also labelled LMK04832-SP_OSCin_P]
LMK_VCXO: C87.2 ; off-sheet LMK_VCXO
LMX1_SYNC: R141.1 ; port LMX1_SYNC
LMX1_SYSREFREQ: R142.2 ; port LMX1_SYSREFREQ
LMX2_SYNC: R209.2 ; port LMX2_SYNC
LMX2_SYSREFREQ: R216.2 ; port LMX2_SYSREFREQ
LMX3_SYNC: R144.2 ; port LMX3_SYNC
LMX3_SYSREFREQ: R148.2 ; port LMX3_SYSREFREQ
OSCout_N: U1.40(OSCout/CLKin2) ; port OSCout_N
OSCout_P: U1.41(~{OSCout}/~{CLKin2}) ; port OSCout_P
RESET: C184.1 R35.2 R343.1 U1.5(RESET/GPO) ; port RESET
SDCLKout1+: R286.2 U1.3(CLKout1)
SDCLKout1+*: R25.1 R30.2 R286.1
SDCLKout1-: R287.2 U1.4(~{CLKout1})
SDCLKout1-*: R27.1 R29.2 R287.1
SDCLKout1_LMK_N: R73.1 ; port SDCLKout1_LMK_N
SDCLKout1_LMK_P: R72.1 ; port SDCLKout1_LMK_P
SDCLKout1_N: R27.2 R73.2 R166.2 ; port SDCLKout1_N
SDCLKout1_P: R25.2 R72.2 R203.2 ; port SDCLKout1_P
SDCLKout3_LMK_N: R92.1 ; port SDCLKout3_LMK_N
SDCLKout3_LMK_P: R84.1 ; port SDCLKout3_LMK_P
SDCLKout3_N: R42.2 R92.2 R208.2 ; port SDCLKout3_N
SDCLKout3_P: R41.2 R84.2 R233.2 ; port SDCLKout3_P
SDCLKout5*_N: R10.1 R56.2 R58.2 R293.1
SDCLKout5*_P: R2.1 R54.2 R59.2 R292.1
SDCLKout5_N: R10.2 R204.1 ; port SDCLKout5_N
SDCLKout5_P: R2.2 R204.2 R209.1 ; port SDCLKout5_P
SDCLKout11_N: R9.2 R143.1 ; port SDCLKout11_N
SDCLKout11_P: R1.2 R141.2 R143.2 ; port SDCLKout11_P
SDCLKout11a_N: R6.2 R9.1 R11.2 R282.1
SDCLKout11a_P: R1.1 R3.2 R12.2 R283.1
SDCLKout13_LMK_N: R136.1 ; port SDCLKout13_LMK_N
SDCLKout13_LMK_P: R135.1 ; port SDCLKout13_LMK_P
SDCLKout13_N: R136.2 R146.1 R357.2 ; port SDCLKout13_N
SDCLKout13_P: R8.2 R135.2 R165.1 ; port SDCLKout13_P
SDCLKout13a_N: R356.2 U1.61(~{CLKout13})
SDCLKout13a_P: R5.2 U1.60(CLKout13)
SDCLKout13b_N: R13.2 R356.1 R357.1
SDCLKout13b_P: R5.1 R8.1 R14.2
Status_LD1: R53.1 R79.1 U1.31(Status_LD1) ; port Status_LD1
Status_LD2: R80.1 U1.48(Status_LD2) ; port Status_LD2
SYNC: C185.1 R190.1 R200.2 R201.2 R202.2 SYNC.1 U1.6(SYNC/SYSREF_REQ) ; port SYNC
SYNC1_IN: R192.1 ; port SYNC1_IN
SYNC1_OUT: R196.1 ; port SYNC1_OUT
SYNC2_IN: R194.1 ; port SYNC2_IN
SYNC2_OUT: R197.2 ; port SYNC2_OUT
NetC8_1: C8.1 R28.2
NetC13_2: C13.2 U1.11(LDObyp1)
NetC14_1: C14.1 U1.12(LDObyp2)
NetC17_2: C17.2 R52.2
NetC19_2: C19.2 C22.2 C83.2 C84.2 L13.1 Y1.4(Vcc)
NetC38_1: C38.1 R103.2 R110.2
NetC39_1: C39.1 R119.1 R120.2
NetC65_1: C65.1 R124.1
NetC65_2: C65.2 J6.1 R123.2
NetC66_1: C66.1 C67.1 R121.1
NetC66_2: C66.2 U6.13(OUT+)
NetC68_1: C68.1 C70.1 R131.1
NetC69_1: C69.1 R125.1
NetC69_2: C69.2 J10.1 R129.2
NetC70_2: C70.2 U6.12(OUT-)
NetC73_2: C73.2 C74.1 R133.2 U6.8(VS-)
NetC75_1: C75.1 C76.2 R134.2 U6.3(VS-)
NetC77_1: C77.1 J18.1 R137.2 R139.2 R140.2 U6.2(CM)
NetC78_1: C78.1 R138.1
NetC86_1: C86.1 Y1.3(OUT)
NetC86_2: C86.2 R170.2
NetC87_1: C87.1 R170.1 R171.2
NetD1_1: D1.1(A) R77.2
NetD2_1: D2.1(A) R78.2
NetD3_1: D3.1(A) R79.2
NetD4_1: D4.1(A) R80.2
NetJ5_1: J5.1 R106.1 U40.1(IN)
NetJ8_1: J8.1 L13.2
NetJ12_1: J12.1 J14.1 R138.2 U6.9(PD)
NetR11_1: R11.1 R12.1 R344.1 R345.2
NetR13_1: R13.1 R14.1 R336.2 R337.2
NetR21_1: R21.1 R22.1 R338.1 R339.1
NetR29_1: R29.1 R30.1 R290.1 R297.2
NetR31_1: R31.1 R32.1 R284.1 R285.2
NetR33_1: R33.1 Y1.1(Vcont)
NetR41_1: R41.1 R50.2 R288.1
NetR42_1: R42.1 R49.2 R289.1
NetR47_1: R47.1 R48.1 R114.1 R291.2
NetR49_1: R49.1 R50.1 R115.1 R298.2
NetR58_1: R58.1 R59.1 R346.2 R366.1
NetR103_1: R103.1 R108.2 R111.2 R116.2
NetR106_2: R106.2 R164.1
NetR111_1: R111.1 R164.2 U40.2(O1)
NetR116_1: R116.1 R117.2 R118.1 R120.1
NetR117_1: R117.1 U40.3(O2)
NetR122_1: R122.1 R124.2 U6.5(IN-)
NetR122_2: R122.2 U6.4(FB+)
NetR125_2: R125.2 R128.1 U6.6(IN+)
NetR128_2: R128.2 U6.7(FB-)
NetR142_1: R142.1 R166.1 R169.2
NetR144_1: R144.1 R167.2
NetR146_2: R146.2 R168.2
NetR148_1: R148.1 R394.2
NetR165_2: R165.2 R168.1 R394.1
NetR167_1: R167.1 R392.1 R393.2
NetR169_1: R169.1 R203.1
NetR191_1: R191.1 R193.1 R195.1 U14.4(Y)
NetR191_2: R191.2 R192.2 U14.1(A)
NetR193_2: R193.2 R196.2 R197.1 R201.1
NetR194_2: R194.2 R195.2 U14.2(B)
NetR208_1: R208.1 R215.2 R216.1
NetR215_1: R215.1 R233.1
NetR282_2: R282.2 U1.57(~{CLKout11})
NetR283_2: R283.2 U1.56(CLKout11)
NetR288_2: R288.2 U1.13(CLKout3)
NetR289_2: R289.2 U1.14(~{CLKout3})
NetR292_2: R292.2 U1.22(CLKout5)
NetR293_2: R293.2 U1.23(~{CLKout5})
NetR391_2: R391.2 R392.2
NetR553_2: R553.2 U1.8(Fin0)
NetR554_2: R554.2 U1.9(~{Fin0})

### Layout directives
differential pair: CLKin0_N, CLKin0_P, CLKin1_N, CLKin1_P, CLKin1c_N, CLKin1c_P, CLKin1d_N, CLKin1d_P, LMK_OSCin_N, LMK_OSCin_P, OSCout_N, OSCout_P
differential pair; differential pair class 100ohm: DCLKout0_N, DCLKout0_P, DCLKout2_N, DCLKout2_P, DCLKout12_N, DCLKout12_P, DCLKout12a_N, DCLKout12a_P, F_CORECLK1_N, F_CORECLK1_P, F_CORECLK2_N, F_CORECLK2_P, F_REFCLK1_N, F_REFCLK1_P, F_REFCLK2_N, F_REFCLK2_P, F_SYSREF1_N, F_SYSREF1_P, F_SYSREF2_N, F_SYSREF2_P, J1J4_N, J1J4_P, J15J13_N, J15J13_P, SDCLKout1_N, SDCLKout1_P, SDCLKout5*_N, SDCLKout5*_P, SDCLKout11a_N, SDCLKout11a_P, SDCLKout13_N, SDCLKout13_P, SDCLKout13a_N, SDCLKout13a_P, SDCLKout13b_N, SDCLKout13b_P

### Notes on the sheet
- Jitter Cleaner / Buffer
- TI Datasheet
- LMK04832-SP
- SMD 5962-17237
- FPGA JESD
- Matched Length

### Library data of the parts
C1 C3-C6 C15 C16 C19 C26 C31 C38 C39 C79 C80 C85-C87 C184-C186 = CMP-0006295-2: CAP, CERM, 0.1 uF, 25 V, +/- 20%, X7R, 0402; Manufacturer: TDK; PartNumber: C1005X7R1E104M050BB; Polarized: N; TaMax_C: 125°C; TaMin_C: -55°C; VDC_V: 25V; Cap_F: 100nF; Value: 0.1uF; Value1: Unknown; U/M: EA; SizeArea_mm2: 0.5; SizeAreaWB_mm2: 3; SizeX_mm: 1; SizeZ_mm: 0.6; AEC Category: Q200
C2 C24 C29 = CMP-0006641-2: CAP, CERM, 0.1 uF, 16 V, +/- 10%, X7R, 0402; PartNumber: GRM155R71C104KA88D; Manufacturer: MuRata; Polarized: N; Value: 0.1uF; U/M: EA; Cap_F: 100nF; Value1: Unknown; VDC_V: 16V; TaMin_C: -55°C; TaMax_C: 125°C; SizeArea_mm2: 0.5; SizeAreaWB_mm2: 3; SizeX_mm: 1; SizeZ_mm: 0.6; AEC Category: Q200
C7 = CMP-0009662-3: CAP, CERM, 47 pF, 25 V, +/- 5%, C0G/NP0, 0201; PartNumber: GRM0335C1E470JA01D; Manufacturer: MuRata; Polarized: N; Value: 47pF; U/M: EA; Value1: Unknown; VDC_V: 25V; TaMin_C: -55°C; TaMax_C: 125°C; Cap_Case: 0201; SizeArea_mm2: 0.18; SizeAreaWB_mm2: 2.08; SizeX_mm: 0.6; SizeY_mm: 0.3; SizeZ_mm: 0.33; AEC Category: Q200
C8 = CMP-0064907-1: CAP, CERM, 3900 pF, 10 V,+/- 10%, X5R, 0201; PartNumber: 0201ZD392KAT2A; Manufacturer: AVX; Polarized: N; Value: 3900pF; U/M: EA; Cap_F: 3.9nF; Value1: Unknown; VDC_V: 10V; TaMin_C: -55°C; TaMax_C: 85°C; SizeArea_mm2: 0.18; SizeAreaWB_mm2: 2.08; SizeX_mm: 0.6; SizeY_mm: 0.3; SizeZ_mm: 0.26; AEC Category: Q200; Green_Lifecycle: Active; Green_REACh: Passed
C10 C11 C23 C27 C28 C32-C35 = CMP-0006300-2: CAP, CERM, 1 uF, 10 V, +/- 10%, X7S, 0402; PartNumber: C1005X7S1A105K050BC; Manufacturer: TDK; Polarized: N; Value: 1uF; U/M: EA; Cap_F: 1µF; ESR_ohm: 0.011416; Value1: 0.011416 ohm; VDC_V: 10V; IRMS_A: 1.483A; TaMin_C: -55°C; TaMax_C: 125°C; SizeArea_mm2: 0.5; SizeAreaWB_mm2: 3; SizeX_mm: 1; SizeZ_mm: 0.6; AEC Category: Q200
C13 = CMP-0007732-2: CAP, CERM, 10 uF, 10 V, +/- 10%, X5R, 0805; Manufacturer: Kemet; PartNumber: C0805C106K8PACTU; Cap_Case: 0805; ESR_ohm: 3m; IRMS_A: 11.43A; Polarized: N; TaMax_C: 85°C; TaMin_C: -55°C; Cap_F: 10µF; Value: 10uF; U/M: EA; Value1: 0.003 ohm; SizeAreaWB_mm2: 6.75; SizeZ_mm: 1.45; SizeX_mm: 2; SizeY_mm: 1.25; SizeArea_mm2: 2.5; AEC Category: Q200
C14 = CMP-0006856-6: CAP, CERM, 0.1 uF, 25 V, +/- 5%, X7R, 0603; Manufacturer: Kemet; PartNumber: C0603C104J3RACTU; Polarized: N; TaMax_C: 125°C; TaMin_C: -55°C; VDC_V: 25V; Cap_F: 100nF; Value: 0.1uF; Value1: Unknown; U/M: EA; AEC Category: Q200; SizeArea_mm2: 1.28; SizeAreaWB_mm2: 4.68; SizeX_mm: 1.6; SizeY_mm: 0.8; SizeZ_mm: 1
C17 = CMP-0006271-2: CAP, CERM, 0.68 uF, 10 V, +/- 10%, X5R, 0402; PartNumber: C1005X5R1A684K050BB; Manufacturer: TDK; Polarized: N; Value: 0.68uF; U/M: EA; Cap_F: 680nF; Value1: Unknown; VDC_V: 10V; TaMin_C: -55°C; TaMax_C: 85°C; SizeArea_mm2: 0.5; SizeAreaWB_mm2: 3; SizeX_mm: 1; SizeZ_mm: 0.6; AEC Category: Q200
C18 C20 C21 = CMP-0006919-4: CAP, CERM, 33 pF, 50 V, +/- 5%, C0G/NP0, 0603; Manufacturer: Kemet; PartNumber: C0603C330J5GACTU; Cap_Case: 0603; Polarized: N; TaMax_C: 125°C; TaMin_C: -55°C; VDC_V: 50V; Value: 33pF; U/M: EA; Value1: Unknown; AEC Category: Q200; SizeArea_mm2: 1.28; SizeAreaWB_mm2: 4.68; SizeX_mm: 1.6; SizeY_mm: 0.8; SizeZ_mm: 1
C22 = CMP-0006196-2: CAP, CERM, 100 pF, 50 V, +/- 1%, C0G/NP0, 0402; PartNumber: 04025A101FAT2A; Manufacturer: AVX; Polarized: N; Value: 100pF; U/M: EA; Value1: Unknown; VDC_V: 50V; TaMin_C: -55°C; TaMax_C: 125°C; SizeArea_mm2: 0.5; SizeAreaWB_mm2: 3; SizeX_mm: 1; SizeZ_mm: 0.6; AEC Category: Q200
C25 C30 = CMP-0006658-2: CAP, CERM, 0.01 uF, 25 V, +/- 10%, X7R, 0402; PartNumber: GRM155R71E103KA01D; Manufacturer: MuRata; Polarized: N; Value: 0.01uF; U/M: EA; Cap_F: 10nF; Value1: Unknown; VDC_V: 25V; TaMin_C: -55°C; TaMax_C: 125°C; SizeArea_mm2: 0.5; SizeAreaWB_mm2: 3; SizeX_mm: 1; SizeZ_mm: 0.6; AEC Category: Q200
C36 C37 = CMP-0009690-3: CAP, CERM, 0.1 uF, 6.3 V, +/- 10%, X5R, 0201; PartNumber: GRM033R60J104KE19D; Manufacturer: MuRata; Polarized: N; Value: 0.1uF; U/M: EA; Cap_F: 100nF; Value1: Unknown; VDC_V: 6.3V; TaMin_C: -55°C; TaMax_C: 85°C; Cap_Case: 0201; SizeArea_mm2: 0.18; SizeAreaWB_mm2: 2.08; SizeX_mm: 0.6; SizeY_mm: 0.3; SizeZ_mm: 0.33; AEC Category: Q200
C40 = CMP-0006295-2: CAP, CERM, 0.1 uF, 25 V, +/- 20%, X7R, 0402; Manufacturer: TDK; PartNumber: C1005X7R1E104M050BB; Polarized: N; TaMax_C: 125°C; TaMin_C: -55°C; Cap_F: 100nF; Value: 0.1uF; Value1: Unknown; U/M: EA; SizeArea_mm2: 0.5; SizeAreaWB_mm2: 3; SizeX_mm: 1; SizeZ_mm: 0.6; AEC Category: Q200
C41 C43 C74 C75 = CMP-0009493-2: CAP, CERM, 2200 pF, 50 V, +/- 20%, X7R, 0306; PartNumber: LLL185R71H222MA01L; Manufacturer: MuRata; Polarized: N; Value: 2200pF; U/M: EA; Cap_F: 2.2nF; Value1: Unknown; TaMin_C: -55°C; TaMax_C: 125°C; SizeArea_mm2: 1.28; SizeAreaWB_mm2: 4.68; SizeX_mm: 0.8; SizeY_mm: 1.6; SizeZ_mm: 0.6; AEC Category: Q200
C42 C63 = CMP-0009490-2: CAP, CERM, 0.01 uF, 25 V, +/- 20%, X7R, 0306; PartNumber: LLL185R71E103MA01L; Manufacturer: MuRata; Polarized: N; Value: 0.01uF; U/M: EA; Cap_F: 10nF; Value1: Unknown; VDC_V: 25V; TaMin_C: -55°C; TaMax_C: 125°C; SizeArea_mm2: 1.28; SizeAreaWB_mm2: 4.68; SizeX_mm: 0.8; SizeY_mm: 1.6; SizeZ_mm: 0.6; AEC Category: Q200
C65 C66 C69 C70 C77 = CMP-0006619-2: CAP, CERM, 1 uF, 35 V, +/- 10%, X5R, 0402; Manufacturer: MuRata; TaMin_C: -55°C; Polarized: N; SizeAreaWB_mm2: 3; Value1: Unknown; U/M: EA; Value: 1uF; TaMax_C: 85°C; SizeZ_mm: 0.6; SizeX_mm: 1; SizeY_mm: 0.5; Cap_F: 1µF; AEC Category: Q200
C67 C68 = CMP-0006206-2: CAP, CERM, 0.3 pF, 50 V, +/- 30%, C0G/NP0, 0402; Manufacturer: Johanson Technology; TaMin_C: -55°C; Polarized: N; SizeAreaWB_mm2: 3; Value1: Unknown; U/M: EA; Value: 0.3pF; TaMax_C: 125°C; SizeZ_mm: 0.6; SizeX_mm: 1; SizeY_mm: 0.5; AEC Category: Q200
C73 C76 = CMP-0009490-2: CAP, CERM, 0.01 uF, 25 V, +/- 20%, X7R, 0306; PartNumber: LLL185R71E103MA01L; Manufacturer: MuRata; Polarized: N; Value: 0.01uF; U/M: EA; Cap_F: 10nF; Value1: Unknown; TaMin_C: -55°C; TaMax_C: 125°C; SizeArea_mm2: 1.28; SizeAreaWB_mm2: 4.68; SizeX_mm: 0.8; SizeY_mm: 1.6; SizeZ_mm: 0.6; AEC Category: Q200
C78 = CMP-0007377-4: CAP, CERM, 0.01 uF, 16 V, +/- 10%, X7R, 0603; Manufacturer: MuRata; TaMin_C: -55°C; Polarized: N; SizeAreaWB_mm2: 4.68; Value1: Unknown; U/M: EA; Value: 0.01uF; TaMax_C: 125°C; SizeZ_mm: 1; SizeX_mm: 1.6; SizeArea_mm2: 1.28; AEC Category: Q200; SizeY_mm: 0.8
C83 = CMP-0006663-2: CAP, CERM, 2200 pF, 25 V, +/- 10%, X7R, 0402; PartNumber: GRM155R71E222KA01D; Manufacturer: MuRata; Polarized: N; Value: 2200pF; U/M: EA; Cap_F: 2.2nF; Value1: Unknown; VDC_V: 25V; TaMin_C: -55°C; TaMax_C: 125°C; SizeArea_mm2: 0.5; SizeAreaWB_mm2: 3; SizeX_mm: 1; SizeZ_mm: 0.6; AEC Category: Q200
C84 = CMP-0006408-2: CAP, CERM, 10 pF, 50 V, +/- 5%, C0G/NP0, 0402; PartNumber: GRM1555C1H100JA01D; Manufacturer: MuRata; Polarized: N; Value: 10pF; U/M: EA; Value1: Unknown; VDC_V: 50V; TaMin_C: -55°C; TaMax_C: 125°C; SizeArea_mm2: 0.5; SizeAreaWB_mm2: 3; SizeX_mm: 1; SizeZ_mm: 0.6; AEC Category: Q200
C355 C356 = CMP-0006658-2: CAP, CERM, 0.01 uF, 25 V, +/- 10%, X7R, 0402; Manufacturer: MuRata; TaMin_C: -55°C; Polarized: N; SizeAreaWB_mm2: 3; Value1: Unknown; U/M: EA; Value: 0.01uF; TaMax_C: 125°C; SizeZ_mm: 0.6; SizeX_mm: 1; SizeY_mm: 0.5; Cap_F: 10nF; AEC Category: Q200
D1-D4 = CMP-0002891-3: LED, Green, SMD; PartNumber: LTST-C191TGKT; Manufacturer: Lite-On; Type: InGaN; Vf_V: 3.2V; Io_A: 20mA; Value1: W
J1-J6 J10 J13-J15 J18 = CMP-0055819-1: Connector, SMA, TH; PartNumber: 142-0701-201; Manufacturer: Cinch Connectivity; CNHeader: FALSE; CT: TRUE; Green_Lifecycle: Not Set; Green_REACh: Incomplete
J8 J12 = CMP-0075483-1: Header, 100mil, 2x1, Gold, TH; Manufacturer: Samtec; Green_REACh: Passed; CT: False; Green_Lifecycle: Active; CNHeader: True
L1-L10 L13 L30 L31 = CMP-0003352-2: Ferrite Bead, 120 ohm @ 100 MHz, 3 A, 0603; PartNumber: BLM18SG121TN1D; Manufacturer: MuRata; Value: 120 ohm; Imax_A: 3A; DCR_ohm: 0.025; Value1: 0.025 ohm; SizeAreaWB_mm2: 4.68; SizeArea_mm2: 1.28; SizeX_mm: 1.6; SizeY_mm: 0.8; SizeZ_mm: 1; ZTyp@100MHz_Ohm: 120
R1-R4 R6-R10 R19 R20 R25-R27 R33 R41 R42 R54-R57 R62 R63 R68-R76 R81 R84 R92 R114 R115 R126 R127 R130 R132 R135 R136 R141 R142 R144 R146 R148 R165-R167 R182-R184 R191-R197 R200-R203 R208 R209 R216 R233 R284 R285 R290 R291 R297 R298 R335-R339 R344-R346 R357 R366 R391 R393 R394 = CMP-0026822-3: RES, 0, 5%, 0.063 W, AEC-Q200 Grade 0, 0402; PartNumber: CRCW04020000Z0ED; Manufacturer: Vishay-Dale; Value: 0; Value_Code: 0000; Power_W: 63mW; Value2: 0.063W; VDC_V: 50V; TempCo: 200 ppm/C; SizeArea_mm2: 0.5; SizeX_mm: 1; SizeZ_mm: 0.6; EIA_Code: E24; AEC Category: Q200; AEC Qualified: Y
R5 R13 R14 R21 R22 R29-R32 R47-R50 R286-R289 R356 = CMP-0026833-3: RES, 120, 5%, 0.063 W, AEC-Q200 Grade 0, 0402; PartNumber: CRCW0402120RJNED; Manufacturer: Vishay-Dale; Value: 120; Value_Code: 120R; Power_W: 63mW; Value2: 0.063W; VDC_V: 50V; TempCo: 200 ppm/C; SizeArea_mm2: 0.5; SizeX_mm: 1; SizeZ_mm: 0.6; EIA_Code: E24; AEC Category: Q200; AEC Qualified: Y; AEC Grade: 0
R11 R12 R15 R16 R23 R24 R60 R61 R64-R67 = CMP-0026882-3: RES, 240, 5%, 0.063 W, AEC-Q200 Grade 0, 0402; PartNumber: CRCW0402240RJNED; Manufacturer: Vishay-Dale; Value: 240; Value_Code: 240R; Power_W: 63mW; Value2: 0.063W; VDC_V: 50V; TempCo: 200 ppm/C; SizeArea_mm2: 0.5; SizeX_mm: 1; SizeZ_mm: 0.6; EIA_Code: E24; AEC Category: Q200; AEC Qualified: Y; AEC Grade: 0
R17 R18 R58 R59 = CMP-0026878-3: RES, 220, 5%, 0.063 W, AEC-Q200 Grade 0, 0402; PartNumber: CRCW0402220RJNED; Manufacturer: Vishay-Dale; Value: 220; Value_Code: 220R; Power_W: 63mW; Value2: 0.063W; VDC_V: 50V; TempCo: 200 ppm/C; SizeArea_mm2: 0.5; SizeX_mm: 1; SizeZ_mm: 0.6; EIA_Code: E24; AEC Category: Q200; AEC Qualified: Y; AEC Grade: 0
R28 = CMP-0027814-1: RES, 620, 1%, 0.05 W, 0201; PartNumber: RC0201FR-07620RL; Manufacturer: Yageo America; Value: 620; Value_Code: 620R; Power_W: 50mW; Value2: 0.05W; VDC_V: 25V; TempCo: 200 ppm/C; SizeArea_mm2: 0.18; SizeX_mm: 0.6; SizeY_mm: 0.3; SizeZ_mm: 0.26; U/M: EA; AEC Category: Q200; AEC Qualified: N
R35 R343 = CMP-0026658-1: RES, 10.0 k, 1%, 0.1 W, 0402; PartNumber: ERJ-2RKF1002X; Manufacturer: Panasonic; Value: 10.0k; Res_ohm: 10k; Value_Code: 10k0; Power_W: 100mW; Value2: 0.1W; VDC_V: 50V; TempCo: 100 ppm/C; SizeArea_mm2: 0.5; SizeX_mm: 1; SizeZ_mm: 0.6; EIA_Code: E96; U/M: EA; AEC Category: Q200
R52 = CMP-0027649-1: RES, 39.0 k, 1%, 0.05 W, 0201; PartNumber: RC0201FR-0739KL; Manufacturer: Yageo America; Value: 39.0k; Res_ohm: 39k; Value_Code: 39k0; Power_W: 50mW; Value2: 0.05W; VDC_V: 25V; TempCo: 200 ppm/C; SizeArea_mm2: 0.18; SizeX_mm: 0.6; SizeY_mm: 0.3; SizeZ_mm: 0.26; U/M: EA; AEC Category: Q200; AEC Qualified: N
R53 = CMP-0025825-4: RES, 51, 5%, 0.1 W, AEC-Q200 Grade 0, 0603; Manufacturer: Vishay-Dale; PartNumber: CRCW060351R0JNEA; VDC_V: 75V; Power_W: 100mW; Value_Code: 51R0; Value2: 0.1W; EIA_Code: E24; TempCo: 200 ppm/C; AEC Category: Q200; AEC Grade: 0; AEC Qualified: Y; SizeArea_mm2: 1.28; SizeX_mm: 1.6; SizeY_mm: 0.8; SizeZ_mm: 1
R77-R80 = CMP-0022588-5: RES, 750, 1%, 0.1 W, AEC-Q200 Grade 0, 0603; PartNumber: CRCW0603750RFKEA; Manufacturer: Vishay-Dale; Value: 750; Value_Code: 750R; Power_W: 100mW; Value2: 0.1W; VDC_V: 75V; TempCo: 100 ppm/C; SizeArea_mm2: 1.28; SizeX_mm: 1.6; SizeY_mm: 0.8; SizeZ_mm: 1; EIA_Code: E96; AEC Category: Q200; AEC Qualified: Y; AEC Grade: 0
R98 R101 = CMP-0065361-1: RES, 0, 5%, .05 W, AEC-Q200 Grade 0, 0201; Manufacturer: Panasonic; PartNumber: ERJ-1GN0R00C; Power_W: 50mW; Value: 0; U/M: EA; Value_Code: 0000; Value2: .05W; EIA_Code: E24; TempCo: ppm/C; SizeArea_mm2: 0.18; SizeX_mm: 0.6; SizeY_mm: 0.3; SizeZ_mm: 0.26; AEC Category: Q200; AEC Qualified: Y; Green_Lifecycle: Not Set; Green_REACh: Incomplete
R99 R100 = CMP-0027139-3: RES, 51, 5%, 0.05 W, 0201; Manufacturer: Yageo America; Power_W: 50mW; TempCo: 200 ppm/C; Value_Code: 51R0; U/M: EA; Value: 51; EIA_Code: E24; SizeX_mm: 0.6; SizeY_mm: 0.3; SizeZ_mm: 0.26; Value2: 0.05W; SizeArea_mm2: 0.18; AEC Qualified: N; VDC_V: 25V; AEC Category: Q200
R103 R106 R111 R117 R120 R164 R553-R556 = CMP-0065361-1: RES, 0, 5%, .05 W, AEC-Q200 Grade 0, 0201; Manufacturer: Panasonic; Power_W: 50mW; Green_Lifecycle: Not Set; TempCo: ppm/C; Value_Code: 0000; Green_REACh: Incomplete; U/M: EA; Value: 0; EIA_Code: E24; SizeX_mm: 0.6; SizeY_mm: 0.3; SizeZ_mm: 0.26; Value2: .05W; SizeArea_mm2: 0.18; AEC Qualified: Y; AEC Category: Q200
R108 R110 R118 R119 R138 = CMP-0022448-4: RES, 49.9, 1%, 0.1 W, AEC-Q200 Grade 0, 0603; Manufacturer: Vishay-Dale; Power_W: 100mW; TempCo: 100 ppm/C; Value_Code: 49R9; Value: 49.9; EIA_Code: E96; SizeX_mm: 1.6; SizeY_mm: 0.8; SizeZ_mm: 1; Value2: 0.1W; SizeArea_mm2: 1.28; AEC Qualified: Y; VDC_V: 75V; AEC Category: Q200; AEC Grade: 0
R116 R143 R145 R168-R170 R204 R215 R392 = CMP-0025951-3: RES, 100, 1%, 0.063 W, AEC-Q200 Grade 0, 0402; Manufacturer: Vishay-Dale; Power_W: 63mW; TempCo: 100 ppm/C; Value_Code: 100R; Value: 100; EIA_Code: E96; SizeX_mm: 1; SizeY_mm: 0.5; SizeZ_mm: 0.6; Value2: 0.063W; AEC Qualified: Y; VDC_V: 50V; AEC Category: Q200; AEC Grade: 0
R121 R131 = CMP-0026368-2: RES, 40.2, 1%, 0.063 W, AEC-Q200 Grade 0, 0402; Manufacturer: Vishay-Dale; Power_W: 63mW; TempCo: 100 ppm/C; Value_Code: 40R2; Value: 40.2; EIA_Code: E96; SizeX_mm: 1; SizeY_mm: 0.5; SizeZ_mm: 0.6; Value2: 0.063W; AEC Qualified: Y; VDC_V: 50V; AEC Category: Q200; AEC Grade: 0
R122 R128 = CMP-0026159-2: RES, 200, 1%, 0.063 W, AEC-Q200 Grade 0, 0402; Manufacturer: Vishay-Dale; Power_W: 63mW; TempCo: 100 ppm/C; Value_Code: 200R; Value: 200; EIA_Code: E96; SizeX_mm: 1; SizeY_mm: 0.5; SizeZ_mm: 0.6; Value2: 0.063W; AEC Qualified: Y; VDC_V: 50V; AEC Category: Q200; AEC Grade: 0
R123 R129 = CMP-0026853-5: RES, 1.1 k, 5%, 0.063 W, AEC-Q200 Grade 0, 0402; Manufacturer: Vishay-Dale; Power_W: 63mW; TempCo: 200 ppm/C; Value_Code: 1k10; Value: 1.1k; EIA_Code: E24; SizeX_mm: 1; SizeY_mm: 0.5; SizeZ_mm: 0.6; Value2: 0.063W; AEC Qualified: Y; VDC_V: 50V; AEC Category: Q200; AEC Grade: 0
R124 R125 = CMP-0025994-3: RES, 12.1, 1%, 0.063 W, AEC-Q200 Grade 0, 0402; Manufacturer: Vishay-Dale; Power_W: 63mW; TempCo: 100 ppm/C; Value_Code: 12R1; Value: 12.1; EIA_Code: E96; SizeX_mm: 1; SizeY_mm: 0.5; SizeZ_mm: 0.6; Value2: 0.063W; AEC Qualified: Y; VDC_V: 50V; AEC Category: Q200; AEC Grade: 0
R133 R134 = CMP-0026822-3: RES, 0, 5%, 0.063 W, AEC-Q200 Grade 0, 0402; Manufacturer: Vishay-Dale; VDC_V: 50V; Power_W: 63mW; Value: 0; Value_Code: 0000; Value2: 0.063W; EIA_Code: E24; TempCo: 200 ppm/C; SizeArea_mm2: 0.5; SizeX_mm: 1; SizeZ_mm: 0.6; AEC Category: Q200; AEC Qualified: Y
R137 R140 = CMP-0022109-5: RES, 1.00 k, 1%, 0.1 W, AEC-Q200 Grade 0, 0603; Manufacturer: Vishay-Dale; Power_W: 100mW; TempCo: 100 ppm/C; Value_Code: 1k00; Value: 1.00k; EIA_Code: E96; Res_ohm: 1k; SizeX_mm: 1.6; SizeY_mm: 0.8; SizeZ_mm: 1; Value2: 0.1W; SizeArea_mm2: 1.28; AEC Qualified: Y; VDC_V: 75V; AEC Category: Q200; AEC Grade: 0
R139 = CMP-0026658-1: RES, 10.0 k, 1%, 0.1 W, 0402; Manufacturer: Panasonic; Power_W: 100mW; TempCo: 100 ppm/C; Value_Code: 10k0; U/M: EA; Value: 10.0k; EIA_Code: E96; Res_ohm: 10k; SizeX_mm: 1; SizeY_mm: 0.5; SizeZ_mm: 0.6; Value2: 0.1W; VDC_V: 50V; AEC Category: Q200
R171 = CMP-0023294-5: RES, 82.0, 1%, 0.1 W, 0603; PartNumber: RC0603FR-0782RL; Manufacturer: Yageo; Value: 82.0; Res_ohm: 82; Value_Code: 82R0; Power_W: 100mW; Value2: 0.1W; VDC_V: 75V; TempCo: 100 ppm/C; SizeArea_mm2: 1.28; SizeX_mm: 1.6; SizeY_mm: 0.8; SizeZ_mm: 1; AEC Category: Q200; AEC Qualified: N; SizeAreaWB_mm2: 4.68
R190 = CMP-0026936-3: RES, 47, 5%, 0.063 W, AEC-Q200 Grade 0, 0402; PartNumber: CRCW040247R0JNED; Manufacturer: Vishay-Dale; Value: 47; Value_Code: 47R0; Power_W: 63mW; Value2: 0.063W; VDC_V: 50V; TempCo: 200 ppm/C; SizeArea_mm2: 0.5; SizeX_mm: 1; SizeZ_mm: 0.6; EIA_Code: E24; AEC Category: Q200; AEC Qualified: Y; AEC Grade: 0
R282 R283 R292 R293 = CMP-0026164-2: RES, 20.0, 1%, 0.063 W, AEC-Q200 Grade 0, 0402; PartNumber: CRCW040220R0FKED; Manufacturer: Vishay-Dale; Value: 20.0; Res_ohm: 20; Value_Code: 20R0; Power_W: 63mW; Value2: 0.063W; VDC_V: 50V; TempCo: 100 ppm/C; SizeArea_mm2: 0.5; SizeX_mm: 1; SizeZ_mm: 0.6; EIA_Code: E96; AEC Category: Q200; AEC Qualified: Y; AEC Grade: 0
SH-J1 = CMP-0003642-1: Shunt, 100mil, Flash Gold, Black; Manufacturer: Sullins Connector Solutions; Value: 1x2
SYNC = CMP-0055144-2: Test Point, Compact, White, TH; Manufacturer: Keystone Electronics; CNHeader: FALSE; ContactFinish: Silver; CT: TRUE; Green_Lifecycle: Active; Green_REACh: Passed
TP1-TP4 TP83 TP84 = CMP-0055119-1: Terminal, Turret, TH, Double; Manufacturer: Keystone; CT: FALSE; Green_REACh: Passed; CompType: Turret Terminal; Green_Lifecycle: Active
TP5 = CMP-0055152-2: Test Point, Miniature, SMT; Manufacturer: Keystone Electronics; CNHeader: FALSE; Green_Lifecycle: Active; Green_REACh: Passed; CT: TRUE
U1 = CMP-0088226-3: Space Grade Ultra-Low-Noise JESD204B Dual-Loop Clock Jitter Cleaner; Manufacturer: Texas Instruments; AEC Qualified: No; SizeZ_mm: 3.53mm; AEC Category: Q200; CompType: IC
U6 = CMP-0074610-5: Radiation Hardness Assured (RHA) 6.5GHz Ultra Wideband Fully Differential Amplifier, FFK0014A (LCCC-14); Manufacturer: Texas Instruments; SizeZ_mm: 1.87; SizeX_mm: 6.0; SizeY_mm: 5.5; SizeArea_mm2: 33.0; CompType: IC; SizeAreaWB_mm2: 60.0; AEC Category: Q200; AEC Qualified: N; Rating: Space
U14 = CMP-0051584-3: Single 2-Input Positive-AND Gate, DCK0005A, LARGE T&R; Manufacturer: Texas Instruments; tpd @ Nom Voltage(Max)(ns): 4.5,6,4,5; F @ Nom Voltage(Max)(Mhz): 150; ICC @ Nom Voltage(Max)(mA): 0.01; Bits(#): 1; VCC(Min)(V): 1.65; Gate Type: AND; Rating: Catalog; Output Type: CMOS; Voltage(Nom)(V): 1.8,2.5,3.3,5; Technology Family: LVC; VCC(Max)(V): 5.5; Input Type: CMOS/TTL; Schmitt Trigger: No; Output Drive (IOL/IOH)(Max)(mA): 32/-32; Logic: True; AEC Category: Q200; AEC Qualified: N; CompType: IC; SizeAreaWB_mm2: 9.3; SizeArea_mm2: 4.2; SizeX_mm: 2.1; SizeY_mm: 2.0; SizeZ_mm: 1.1
U40 = CMP-0065379-3: Broadband Balun, 500 kHz to 6 GHz; Manufacturer: Marki Microwave; SizeZ_mm: 3.94; SizeX_mm: 8.13; SizeArea_mm2: 66.0969; SizeAreaWB_mm2: 102.6169
Y1 = CMP-0006073-3: VCXO, 100 MHz, 3.3V, SMD; Manufacturer: Crystek Corporation; CompType: Oscillator; TaMin_C: 0°C; TaMax_C: 70°C; Frequency Stability: +/-20ppm; Frequency_Fixed: 100MHz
